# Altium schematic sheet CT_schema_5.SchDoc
size 445 x 328 mm
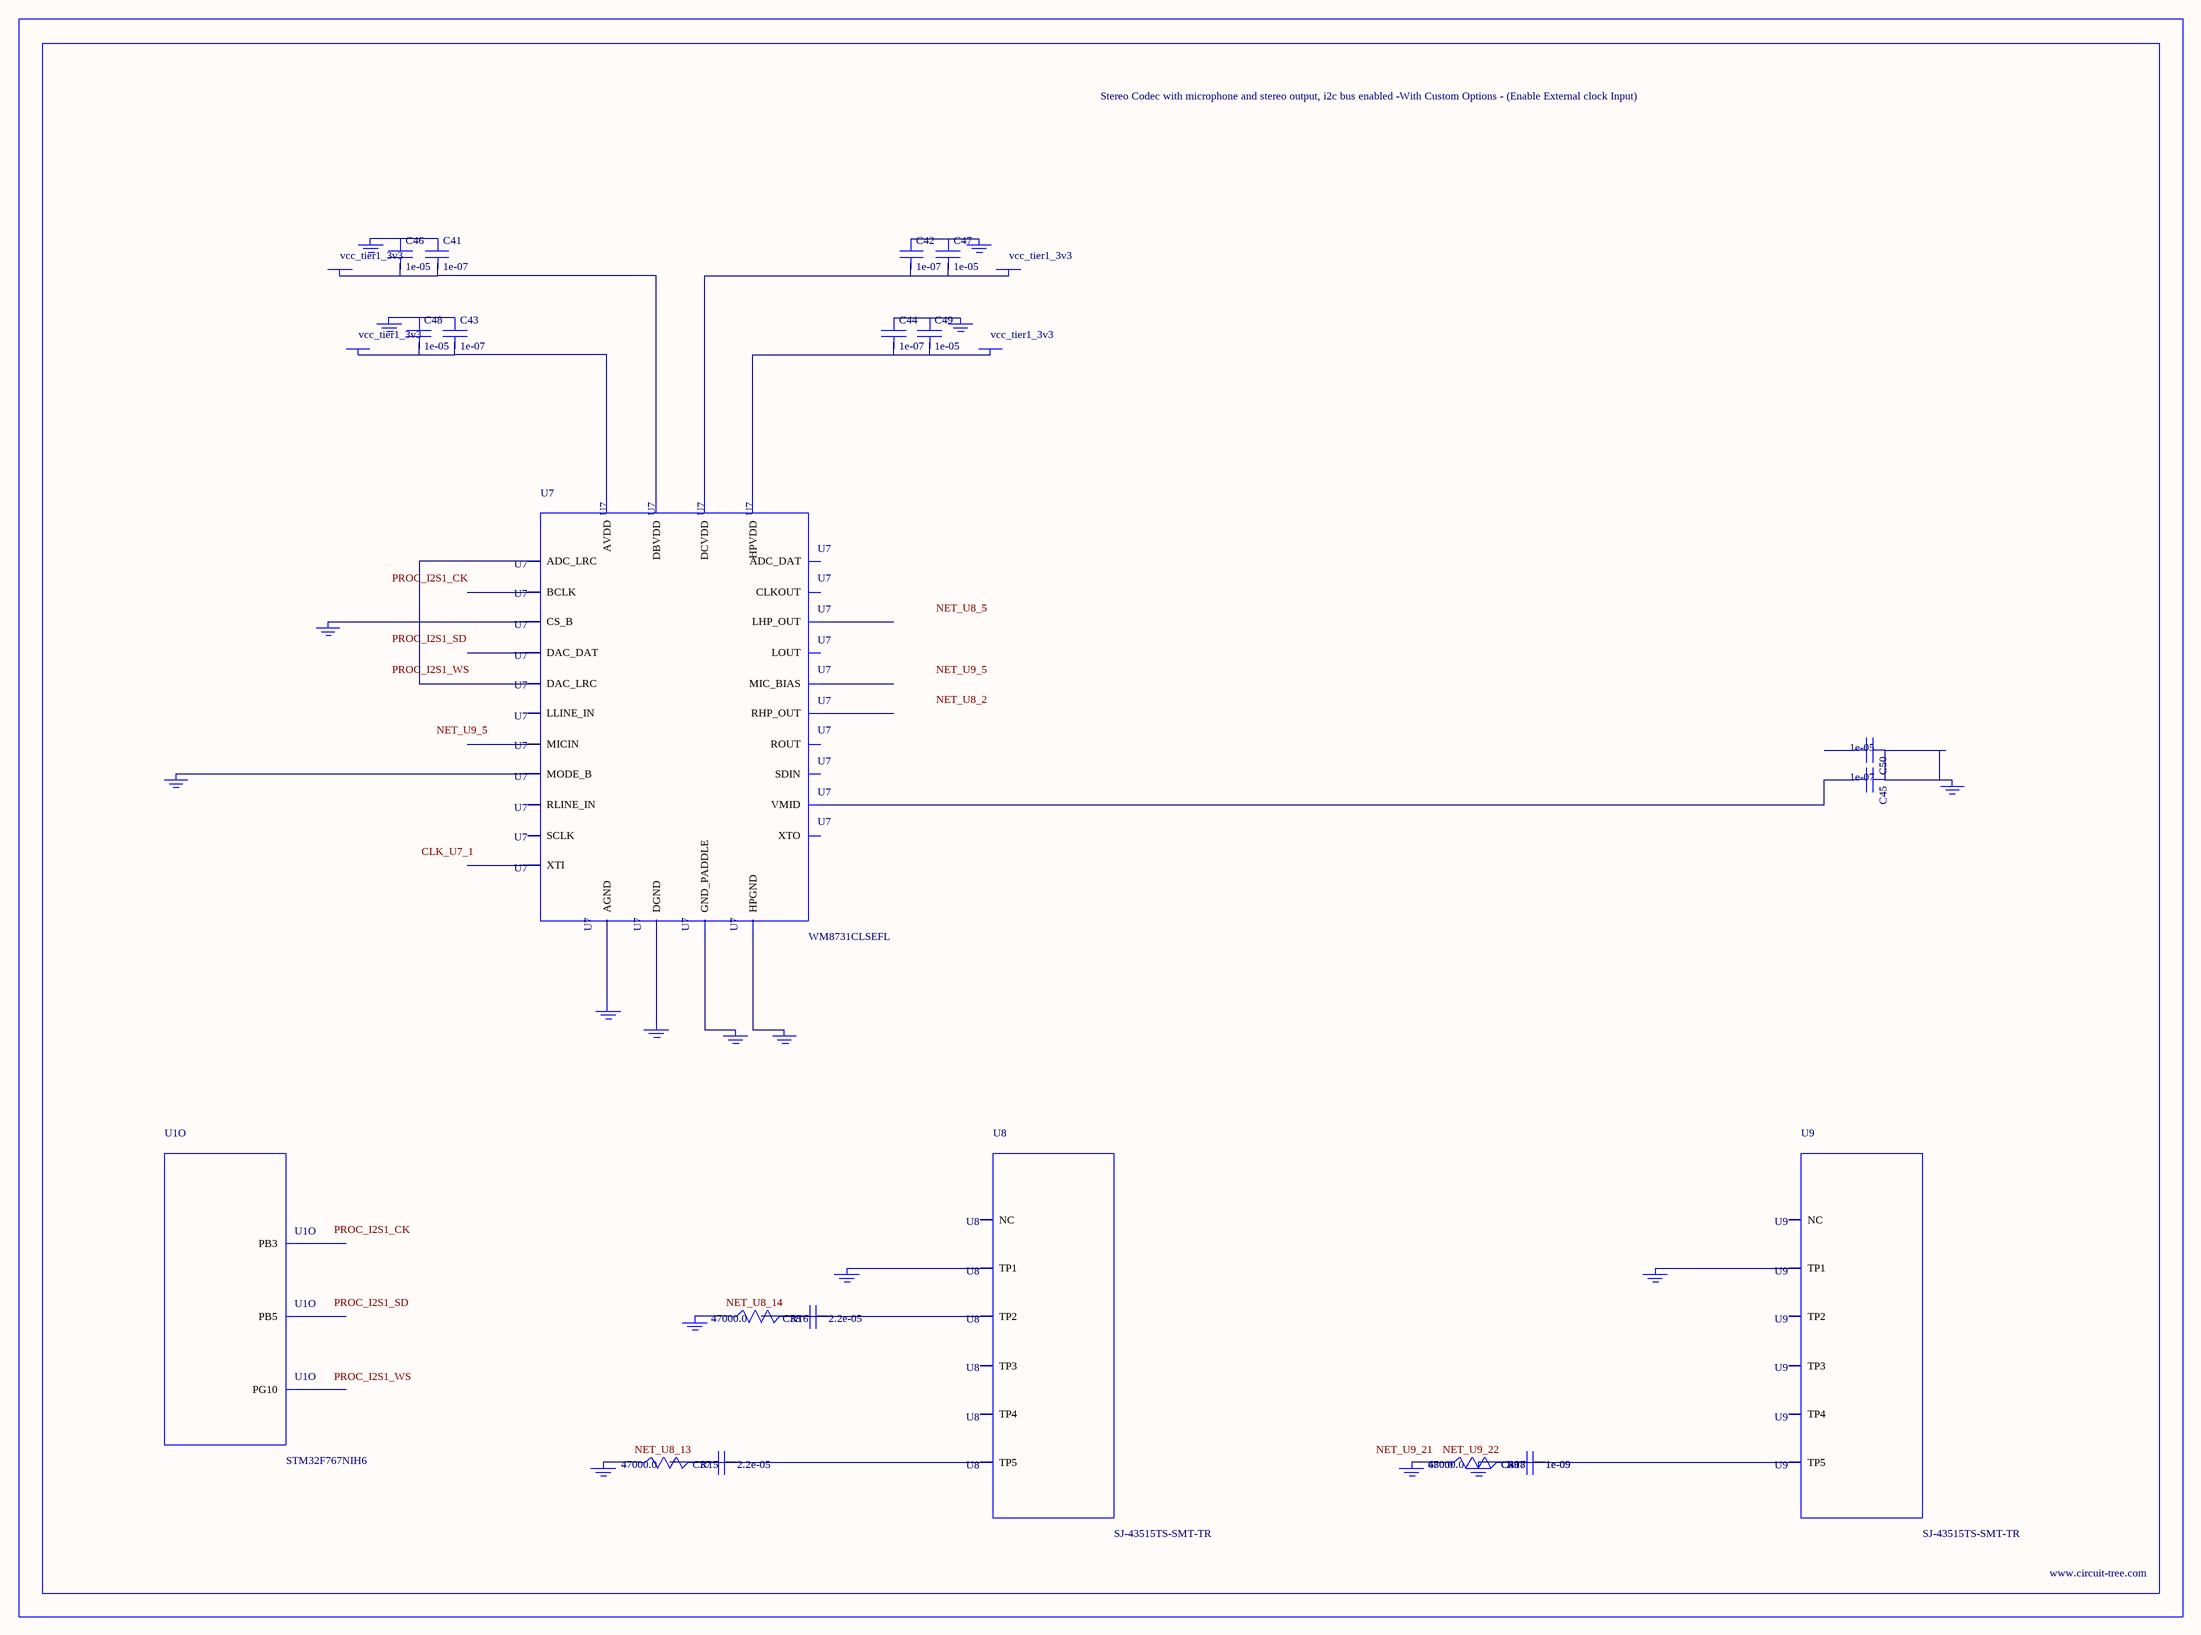
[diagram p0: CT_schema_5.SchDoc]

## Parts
BORDER4  (no value)
C37  2.2e-05  [C1210]
C38  2.2e-05  [C1210]
C39  1e-09  [C0402]
C40  1e-09  [C0402]
C41  1e-07  [C0402]
C42  1e-07  [C0402]
C43  1e-07  [C0402]
C44  1e-07  [C0402]
C45  1e-07  [C0402]
C46  1e-05  [C0805]
C47  1e-05  [C0805]
C48  1e-05  [C0805]
C49  1e-05  [C0805]
C50  1e-05  [C0805]
GND_INSTANCE_4_0  (no value)
GND_INSTANCE_4_1  (no value)
GND_INSTANCE_4_2  (no value)
GND_INSTANCE_4_3  (no value)
GND_INSTANCE_4_4  (no value)
GND_INSTANCE_4_5  (no value)
GND_INSTANCE_4_6  (no value)
GND_INSTANCE_4_7  (no value)
GND_INSTANCE_4_8  (no value)
GND_INSTANCE_4_9  (no value)
GND_INSTANCE_4_10  (no value)
GND_INSTANCE_4_11  (no value)
GND_INSTANCE_4_12  (no value)
GND_INSTANCE_4_13  (no value)
GND_INSTANCE_4_14  (no value)
GND_INSTANCE_4_15  (no value)
GND_INSTANCE_4_16  (no value)
POWER_INSTANCE_4_0  vcc_tier1_3v3
POWER_INSTANCE_4_1  vcc_tier1_3v3
POWER_INSTANCE_4_2  vcc_tier1_3v3
POWER_INSTANCE_4_3  vcc_tier1_3v3
R15  47000.0  [R0603]
R16  47000.0  [R0603]
R17  47000.0  [R0603]
R18  680.0  [R0603]
U1  STM32F767NIH6  [TFBGA216]  (part O of 16)
U7  WM8731CLSEFL  [QFN-28]
U8  SJ-43515TS-SMT-TR  [SJ-43515TS-SMT-TR]
U9  SJ-43515TS-SMT-TR  [SJ-43515TS-SMT-TR]

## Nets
NetC37_1: C37.1 C37.2 R15.2 U8.5(TP5)
NetC38_1: C38.1 C38.2 R16.2 U8.2(TP2)
NetC39_1: C39.1 C39.2 C40.1 C40.2 GND_INSTANCE_4_16.0(GND) R17.2 R18.2 U9.5(TP5)
NetC41_1: C41.1 C46.1 GND_INSTANCE_4_1.0(GND)
NetC41_2: C41.2 C46.2 POWER_INSTANCE_4_1.0(PWR) U7.5(DBVDD)
NetC42_1: C42.1 C47.1 GND_INSTANCE_4_0.0(GND)
NetC42_2: C42.2 C47.2 POWER_INSTANCE_4_0.0(PWR) U7.3(DCVDD)
NetC43_1: C43.1 C48.1 GND_INSTANCE_4_4.0(GND)
NetC43_2: C43.2 C48.2 POWER_INSTANCE_4_3.0(PWR) U7.18(AVDD)
NetC44_1: C44.1 C49.1 GND_INSTANCE_4_2.0(GND)
NetC44_2: C44.2 C49.2 POWER_INSTANCE_4_2.0(PWR) U7.12(HPVDD)
NetC45_1: C45.1 C50.1 GND_INSTANCE_4_5.0(GND)
NetC45_2: C45.2 U7.20(VMID)
NetGND_INSTANCE_4_3_0: GND_INSTANCE_4_3.0(GND) U7.15(HPGND)
NetGND_INSTANCE_4_6_0: GND_INSTANCE_4_6.0(GND) U7.25(MODE_B)
NetGND_INSTANCE_4_7_0: GND_INSTANCE_4_7.0(GND) U7.26(CS_B)
NetGND_INSTANCE_4_8_0: GND_INSTANCE_4_8.0(GND) U7.29(GND_PADDLE)
NetGND_INSTANCE_4_9_0: GND_INSTANCE_4_9.0(GND) U7.4(DGND)
NetGND_INSTANCE_4_10_0: GND_INSTANCE_4_10.0(GND) U7.19(AGND)
NetGND_INSTANCE_4_11_0: GND_INSTANCE_4_11.0(GND) U8.1(TP1)
NetGND_INSTANCE_4_12_0: GND_INSTANCE_4_12.0(GND) R16.1
NetGND_INSTANCE_4_13_0: GND_INSTANCE_4_13.0(GND) R15.1
NetGND_INSTANCE_4_14_0: GND_INSTANCE_4_14.0(GND) U9.1(TP1)
NetGND_INSTANCE_4_15_0: GND_INSTANCE_4_15.0(GND) R17.1 R18.1
NetU7_9: U7.9(DAC_LRC) U7.11(ADC_LRC)

Not connected (* = marked no-connect by the designer): C50 2; U1 A8(PB5) A10(PB3) C8(PG10); U7 1(XTI) 2(XTO) 6(CLKOUT) 7(BCLK) 8(DAC_DAT) 10(ADC_DAT) 13(LHP_OUT) 14(RHP_OUT) 16(LOUT) 17(ROUT) 21(MIC_BIAS) 22(MICIN) 23(RLINE_IN) 24(LLINE_IN) 27(SDIN) 28(SCLK); U8 3(TP3) 4(TP4) 6(NC); U9 2(TP2) 3(TP3) 4(TP4) 6(NC)

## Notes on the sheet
- Labels drawn without touching a wire or pin: CLK_U7_1, NET_U8_2, NET_U8_5, NET_U8_13, NET_U8_14, NET_U9_5, NET_U9_21, NET_U9_22, PROC_I2S1_CK, PROC_I2S1_SD, PROC_I2S1_WS

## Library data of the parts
BORDER4 = BORDER_PAGE4
C37 C38 = C1210C224K5RACTU
C39 C40 = C0402C102K3RAC
C41-C45 = C0402C104K3RACTU
C46-C50 = C0805C106K8RACTU
GND_INSTANCE_4_0-GND_INSTANCE_4_16 = GND
POWER_INSTANCE_4_0-POWER_INSTANCE_4_3 = PWR
R15-R17 = RC0603JR-0747KL
R18 = RC0603JR-07680RL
